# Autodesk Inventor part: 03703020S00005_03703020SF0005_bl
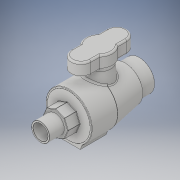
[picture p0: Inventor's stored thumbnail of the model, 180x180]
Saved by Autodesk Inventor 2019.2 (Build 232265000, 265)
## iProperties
Created: 2022-04
Part Number: 03703020S00005_03703020SF0005_bl
Material: Generic
Description: PA Ball Valve Female 1/2'' x Male 1/2''
Document SubType Name: Modeling
Designer: Lenora
Density: 1 g/cm^3
Appearance: Default
Author: Lenora
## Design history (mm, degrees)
derived "0370302.ipt"
feature "Solid1::0370302.ipt" dims "ScaleForDerivedMember" = 10
tag "TaggingFeature1"
body "Solid1"
other parameters: "d0" = 114 [user parameter], "d1" = 17 [user parameter], "d2" = 18 [user parameter], "d3" = 1.8 [user parameter], "d4" = 20.955 [user parameter], "d8" = 18.631 [user parameter], "d9" = 27 [user parameter], "d10" = 100 deg [user parameter], "d12" = 13.6 [user parameter], "d14" = 17.55 [user parameter], "d15" = 20.25 [user parameter], "d16" = 46.74 [user parameter], "d17" = 17 [user parameter], "d19" = 1 [user parameter], "d20" = 28.5 [user parameter], "d21" = 54 [user parameter], "d22" = 85 deg [user parameter], "d23" = 16.2 [user parameter], "d24" = 30.78 [user parameter], "d25" = 1 [user parameter], "d26" = 14.25 [user parameter], "d27" = 53 [user parameter], "d34" = 20.52 [user parameter], "d35" = 11.4 [user parameter], "d37" = 0 [user parameter], "d39" = 360 deg [user parameter], "d41" = 49.29 [user parameter], "d42" = 80 deg [user parameter], "d43" = 27 [user parameter], "d44" = 26.5 [user parameter], "d45" = 70 deg [user parameter], "d46" = 70 deg [user parameter], "d48" = 0 [user parameter], "d50" = 0 [user parameter], "d51" = 0.5 [user parameter], "d52" = 0.25 [user parameter], "d55" = 2 [user parameter], "d56" = 2 [user parameter], "d57" = 2 [user parameter], "Rc" = 18.631 [user parameter], "R" = 20.955 [user parameter], "A1" = 27 [user parameter], "A2" = 54 [user parameter], "H_" = 114 [user parameter], "l1" = 18 [user parameter], "l2" = 17 [user parameter], "B" = 27 [user parameter], "E_" = 53 [user parameter]
